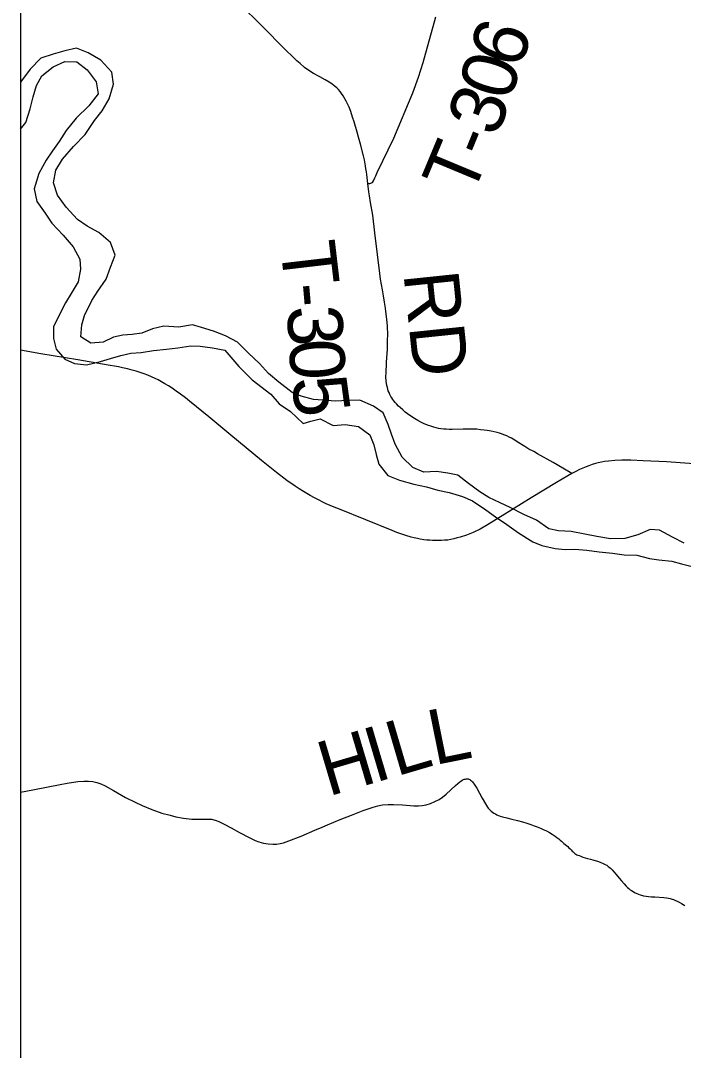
# Model space of a CAD drawing. Extents: x -10.5 to 40.6, y -3.2 to 22.
# Drawn here: x -10.544 to -9.859, y 17.758 to 18.823 of the extents above; entities that cross this region are included whole.
import ezdxf

# ---------------------------------------------------------------- set-up
doc = ezdxf.new("R2010")
doc.units = 0
for name, color, linetype in [('GM_X_Major_River', 7, 'Continuous'), ('GM_X_State_Route', 7, 'Continuous'), ('GM_X_Township_Road', 7, 'Continuous'), ('GM_X_Township_Road_Text', 7, 'Continuous'), ('GM_X_Township_Text', 7, 'Continuous')]:
    doc.layers.add(name, color=color, linetype=linetype)

msp = doc.modelspace()

# ---------------------------------------------------------------- linework, layer by layer
at = {"layer": 'GM_X_Major_River'}
for points in [[(-10.1795, 18.4239), (-10.1936, 18.4301), (-10.2057, 18.4296), (-10.219, 18.429), (-10.2319, 18.43), (-10.2418, 18.4306), (-10.2543, 18.4343), (-10.2638, 18.4379), (-10.2776, 18.4487), (-10.288, 18.4577), (-10.2976, 18.4678), (-10.3088, 18.4786), (-10.3203, 18.4899), (-10.3325, 18.4965), (-10.3451, 18.5013), (-10.3573, 18.5053), (-10.3668, 18.5078), (-10.3808, 18.5057), (-10.3963, 18.5067), (-10.408, 18.5039), (-10.419, 18.4995), (-10.4292, 18.4979), (-10.4387, 18.4974), (-10.4485, 18.4953), (-10.459, 18.4899), (-10.4719, 18.489), (-10.4822, 18.4956), (-10.4813, 18.5078), (-10.4784, 18.5177), (-10.471, 18.533), (-10.4647, 18.5429), (-10.4561, 18.5552), (-10.4514, 18.5677), (-10.4466, 18.5799), (-10.4517, 18.5931), (-10.4636, 18.6036), (-10.4758, 18.6099), (-10.4858, 18.617), (-10.4973, 18.6297), (-10.5062, 18.6421), (-10.5106, 18.6549), (-10.5081, 18.6679), (-10.501, 18.6793), (-10.4899, 18.6924), (-10.4779, 18.7047), (-10.4682, 18.7192), (-10.46, 18.7292), (-10.453, 18.7418), (-10.4483, 18.7567), (-10.45, 18.7691), (-10.4615, 18.7815), (-10.4745, 18.7893), (-10.4867, 18.7941), (-10.4988, 18.7912), (-10.5109, 18.788), (-10.5237, 18.7837), (-10.5345, 18.7722), (-10.5445, 18.759)], [(-10.5445, 18.7103), (-10.5391, 18.7171), (-10.5347, 18.7312), (-10.5315, 18.7438), (-10.5279, 18.7556), (-10.5227, 18.7655), (-10.5107, 18.7748), (-10.4986, 18.7802), (-10.4865, 18.78), (-10.4758, 18.7718), (-10.4665, 18.7594), (-10.4644, 18.747), (-10.4741, 18.7343), (-10.4872, 18.7216), (-10.4973, 18.709), (-10.5047, 18.6975), (-10.5114, 18.6879), (-10.5181, 18.6783), (-10.5255, 18.6646), (-10.5306, 18.6486), (-10.5277, 18.6354), (-10.5192, 18.6233), (-10.5123, 18.6132), (-10.5004, 18.6008), (-10.4903, 18.5885), (-10.4833, 18.5757), (-10.4824, 18.5654), (-10.4849, 18.5525), (-10.4923, 18.5403), (-10.4979, 18.5307), (-10.5045, 18.5181), (-10.5104, 18.5059), (-10.5103, 18.4938), (-10.5078, 18.4828), (-10.4986, 18.4723), (-10.4887, 18.4679), (-10.4765, 18.4665), (-10.4618, 18.4701), (-10.4516, 18.4733), (-10.441, 18.4761), (-10.4305, 18.4785), (-10.4198, 18.4794), (-10.407, 18.4815), (-10.3937, 18.4828), (-10.382, 18.4841), (-10.3684, 18.4862), (-10.3589, 18.4859), (-10.346, 18.4842), (-10.3334, 18.4817), (-10.319, 18.4649), (-10.305, 18.451), (-10.2856, 18.4362), (-10.2771, 18.4262), (-10.2654, 18.4184), (-10.2522, 18.406), (-10.2445, 18.4083), (-10.2347, 18.4106)], [(-9.8583, 18.2822), (-9.8705, 18.2885), (-9.8839, 18.2955), (-9.8934, 18.2962), (-9.9062, 18.2907), (-9.9198, 18.2871), (-9.9346, 18.2865), (-9.9487, 18.289), (-9.9612, 18.2914), (-9.9753, 18.2943), (-9.9882, 18.2949), (-9.9984, 18.297), (-10.0111, 18.3059), (-10.024, 18.3118), (-10.0382, 18.3192), (-10.0485, 18.324), (-10.0603, 18.3295), (-10.0698, 18.3351), (-10.0813, 18.3437), (-10.0925, 18.3526), (-10.1027, 18.3544), (-10.1145, 18.3561), (-10.1274, 18.3556), (-10.1388, 18.3603), (-10.15, 18.3712), (-10.1573, 18.3847), (-10.1609, 18.3949), (-10.1644, 18.4048), (-10.1695, 18.4168), (-10.1795, 18.4239)], [(-10.2347, 18.4106), (-10.2213, 18.404), (-10.2088, 18.4049), (-10.1951, 18.4028), (-10.1833, 18.3943), (-10.1793, 18.3837), (-10.1769, 18.3739), (-10.1741, 18.364), (-10.1649, 18.352), (-10.1527, 18.3473), (-10.1378, 18.3433), (-10.1249, 18.3404), (-10.1131, 18.3368), (-10.1013, 18.3347), (-10.0876, 18.3303), (-10.0773, 18.3259), (-10.0635, 18.3166), (-10.0536, 18.3095), (-10.0417, 18.3014), (-10.0298, 18.2928), (-10.0149, 18.2835), (-10.0054, 18.2798), (-9.9917, 18.2766), (-9.9815, 18.2756), (-9.9716, 18.2758), (-9.9591, 18.2748), (-9.9462, 18.2731), (-9.9325, 18.2717), (-9.9203, 18.27), (-9.9075, 18.2698), (-9.8941, 18.2662), (-9.8846, 18.2648), (-9.871, 18.2635), (-9.8611, 18.2609), (-9.8489, 18.2577)]]:
    msp.add_lwpolyline(points, dxfattribs=at)
at = {"layer": 'GM_X_State_Route'}
msp.add_lwpolyline([(-9.8338, 18.3633), (-9.8767, 18.3661), (-9.9009, 18.3674), (-9.9134, 18.3679), (-9.9227, 18.3681), (-9.9302, 18.3677), (-9.9366, 18.3671), (-9.9406, 18.3666), (-9.944, 18.3658), (-9.9472, 18.3652), (-9.9501, 18.3644), (-9.9535, 18.3634), (-9.9569, 18.3621), (-9.9598, 18.3611), (-9.963, 18.3598), (-9.9667, 18.3582), (-9.9704, 18.3563), (-9.9744, 18.3542), (-9.9786, 18.3519), (-9.9905, 18.345), (-10.0165, 18.3291), (-10.0466, 18.3104), (-10.0619, 18.301), (-10.0694, 18.2968), (-10.0767, 18.2933), (-10.0835, 18.2906), (-10.09, 18.2885), (-10.0932, 18.2876), (-10.0964, 18.2867), (-10.0995, 18.286), (-10.1029, 18.2854), (-10.1062, 18.2851), (-10.1092, 18.2849), (-10.1122, 18.2849), (-10.1153, 18.2849), (-10.1186, 18.285), (-10.1214, 18.2851), (-10.1243, 18.2853), (-10.1277, 18.2857), (-10.1312, 18.2863), (-10.1342, 18.2869), (-10.1376, 18.2876), (-10.1408, 18.2885), (-10.1461, 18.2901), (-10.1504, 18.2915), (-10.1554, 18.2933), (-10.1603, 18.2951), (-10.2148, 18.3172), (-10.2203, 18.3194), (-10.2245, 18.3212), (-10.2284, 18.3229), (-10.2321, 18.3247), (-10.2358, 18.3266), (-10.2407, 18.3291), (-10.245, 18.3314), (-10.2486, 18.3335), (-10.2521, 18.3357), (-10.2566, 18.3384), (-10.2605, 18.341), (-10.2691, 18.3471), (-10.2799, 18.3553), (-10.2953, 18.3678), (-10.327, 18.3939), (-10.35, 18.4129), (-10.3697, 18.4291), (-10.3741, 18.4326), (-10.3791, 18.4363), (-10.3835, 18.4395), (-10.3877, 18.4424), (-10.3916, 18.4448), (-10.3952, 18.447), (-10.3988, 18.4491), (-10.4023, 18.4509), (-10.4055, 18.4525), (-10.4091, 18.4541), (-10.4131, 18.4559), (-10.4167, 18.4573), (-10.4209, 18.4588), (-10.425, 18.4601), (-10.4293, 18.4612), (-10.4341, 18.4624), (-10.4392, 18.4636), (-10.4433, 18.4644), (-10.4474, 18.4652), (-10.452, 18.466), (-10.4597, 18.4673), (-10.4854, 18.4716), (-10.5234, 18.4781), (-10.5445, 18.4818)], dxfattribs=at)
at = {"layer": 'GM_X_Township_Road'}
for points in [[(-10.1855, 18.654), (-10.1862, 18.6602), (-10.1865, 18.6633), (-10.1869, 18.6663), (-10.1874, 18.6693), (-10.1878, 18.6724), (-10.189, 18.6785), (-10.1899, 18.6827), (-10.1931, 18.6947), (-10.1951, 18.7019), (-10.1966, 18.7073), (-10.1996, 18.718), (-10.2012, 18.7227), (-10.2032, 18.7285), (-10.2049, 18.7332), (-10.2079, 18.7393), (-10.211, 18.7447), (-10.2126, 18.7473), (-10.2142, 18.7493), (-10.2158, 18.7513), (-10.2175, 18.753), (-10.2202, 18.7552), (-10.2228, 18.7571), (-10.2256, 18.7589), (-10.2297, 18.7613), (-10.2352, 18.7643), (-10.2416, 18.768), (-10.2474, 18.7717), (-10.2509, 18.7742), (-10.2556, 18.7782), (-10.2588, 18.7811), (-10.2621, 18.7842), (-10.2714, 18.793), (-10.2762, 18.7979), (-10.2896, 18.8117), (-10.2988, 18.8209), (-10.3142, 18.8362)], [(-10.1855, 18.654), (-10.1833, 18.654), (-10.1807, 18.6551), (-10.1795, 18.657), (-10.1781, 18.66), (-10.1772, 18.6621), (-10.1757, 18.6654), (-10.1587, 18.7009), (-10.1391, 18.7477), (-10.133, 18.7641), (-10.1282, 18.7793), (-10.1152, 18.8266)], [(-9.9744, 18.3542), (-9.9838, 18.3597), (-9.9937, 18.3655), (-10.0102, 18.3747), (-10.014, 18.3768), (-10.0189, 18.3795), (-10.0232, 18.3821), (-10.0311, 18.3871), (-10.0336, 18.3887), (-10.0369, 18.3906), (-10.0395, 18.3919), (-10.0419, 18.3931), (-10.0447, 18.3942), (-10.0471, 18.3951), (-10.0494, 18.3958), (-10.0519, 18.3965), (-10.0547, 18.3972), (-10.058, 18.3979), (-10.062, 18.3986), (-10.0653, 18.3991), (-10.069, 18.3995), (-10.0727, 18.3999), (-10.076, 18.4001), (-10.0802, 18.4002), (-10.087, 18.4), (-10.0982, 18.3996), (-10.1013, 18.3996), (-10.1044, 18.3999), (-10.107, 18.4001), (-10.1099, 18.4005), (-10.1123, 18.4009), (-10.1148, 18.4014), (-10.1173, 18.4021), (-10.1202, 18.403), (-10.1227, 18.4039), (-10.1254, 18.4049), (-10.128, 18.406), (-10.1305, 18.4073), (-10.1337, 18.409), (-10.1373, 18.4111), (-10.1411, 18.4136), (-10.1444, 18.416), (-10.1467, 18.4177), (-10.1492, 18.4199), (-10.1519, 18.4223), (-10.1538, 18.424), (-10.1558, 18.4261), (-10.1573, 18.4277), (-10.1585, 18.4292), (-10.1596, 18.4306), (-10.1607, 18.4325), (-10.1617, 18.434), (-10.1626, 18.4358), (-10.1635, 18.4379), (-10.1643, 18.4398), (-10.1653, 18.4433), (-10.1658, 18.4453), (-10.1662, 18.4476), (-10.1665, 18.4495), (-10.1666, 18.4512), (-10.1667, 18.4527), (-10.1667, 18.4552), (-10.1666, 18.4574), (-10.166, 18.4692), (-10.1653, 18.4828), (-10.1651, 18.4883), (-10.165, 18.492), (-10.1649, 18.4976), (-10.1652, 18.5066), (-10.1658, 18.5137), (-10.1668, 18.5216), (-10.1673, 18.5252), (-10.1682, 18.5313), (-10.1694, 18.538), (-10.1704, 18.5441), (-10.1714, 18.5496), (-10.1722, 18.5551), (-10.1731, 18.5612), (-10.1756, 18.5806), (-10.1781, 18.603), (-10.1803, 18.6213), (-10.1826, 18.6346), (-10.1836, 18.6414), (-10.1843, 18.6456), (-10.1855, 18.654)], [(-10.5445, 18.0246), (-10.5317, 18.0271), (-10.5159, 18.0303), (-10.5037, 18.0327), (-10.4963, 18.034), (-10.4853, 18.0357), (-10.4791, 18.0362), (-10.4742, 18.0362), (-10.4698, 18.0357), (-10.4656, 18.0348), (-10.4615, 18.0334), (-10.457, 18.0313), (-10.4483, 18.0265), (-10.4359, 18.0193), (-10.426, 18.0142), (-10.4187, 18.0108), (-10.4089, 18.0069), (-10.3984, 18.0031), (-10.39, 18.0007), (-10.384, 17.9993), (-10.376, 17.9979), (-10.3674, 17.9969), (-10.3611, 17.9966), (-10.3554, 17.9968), (-10.3508, 17.9967), (-10.347, 17.9966), (-10.3432, 17.9958), (-10.3395, 17.9944), (-10.3339, 17.9916), (-10.3266, 17.9876), (-10.318, 17.9828), (-10.3082, 17.9777), (-10.3021, 17.9748), (-10.2981, 17.9733), (-10.2933, 17.972), (-10.2884, 17.9713), (-10.2835, 17.9709), (-10.2798, 17.971), (-10.2761, 17.9715), (-10.2725, 17.9724), (-10.2672, 17.9742), (-10.2544, 17.9792), (-10.2402, 17.9853), (-10.2328, 17.9885), (-10.2271, 17.991), (-10.214, 17.9964), (-10.2025, 18.001), (-10.1904, 18.0056), (-10.1798, 18.0092), (-10.175, 18.0105), (-10.1702, 18.0114), (-10.1646, 18.0119), (-10.159, 18.0119), (-10.1497, 18.0114), (-10.1379, 18.0105), (-10.133, 18.0105), (-10.1293, 18.0109), (-10.125, 18.0117), (-10.1208, 18.013), (-10.1162, 18.0149), (-10.1118, 18.0172), (-10.1082, 18.0196), (-10.1044, 18.0227), (-10.0947, 18.0315), (-10.0925, 18.0336), (-10.0905, 18.0352), (-10.0892, 18.0362), (-10.088, 18.037), (-10.0868, 18.0376), (-10.0857, 18.038), (-10.0849, 18.0382), (-10.0839, 18.0384), (-10.0826, 18.0385), (-10.0818, 18.0383), (-10.0809, 18.038), (-10.0801, 18.0376), (-10.0793, 18.0371), (-10.0783, 18.0364), (-10.0774, 18.0355), (-10.0765, 18.0342), (-10.0756, 18.033), (-10.0729, 18.0288), (-10.0673, 18.0185), (-10.0639, 18.0125), (-10.0627, 18.0108), (-10.0617, 18.0092), (-10.0609, 18.0082), (-10.0602, 18.0075), (-10.059, 18.0061), (-10.0579, 18.0051), (-10.0567, 18.0041), (-10.0552, 18.0031), (-10.0536, 18.0021), (-10.0521, 18.0013), (-10.0503, 18.0006), (-10.0485, 18), (-10.0462, 17.9992), (-10.0416, 17.998), (-10.0366, 17.9968), (-10.0306, 17.9953), (-10.0257, 17.994), (-10.021, 17.9926), (-10.0168, 17.9912), (-10.0134, 17.99), (-10.0104, 17.9889), (-10.0071, 17.9875), (-10.0042, 17.9862), (-10.0009, 17.9845), (-9.9978, 17.9828), (-9.995, 17.9811), (-9.9917, 17.979), (-9.9899, 17.9776), (-9.988, 17.9763), (-9.9865, 17.9751), (-9.9853, 17.974), (-9.9842, 17.973), (-9.9827, 17.9717), (-9.9813, 17.9705), (-9.9799, 17.9694), (-9.9788, 17.9684), (-9.9776, 17.9672), (-9.9764, 17.9662), (-9.9752, 17.9649), (-9.9741, 17.9638), (-9.9731, 17.9629), (-9.9721, 17.962), (-9.9713, 17.9613), (-9.9703, 17.9606), (-9.9692, 17.96), (-9.9682, 17.9595), (-9.9671, 17.959), (-9.9654, 17.9584), (-9.963, 17.9576), (-9.9608, 17.9569), (-9.9582, 17.9562), (-9.9553, 17.9553), (-9.9529, 17.9546), (-9.9469, 17.9528), (-9.9446, 17.952), (-9.9429, 17.9513), (-9.9415, 17.9507), (-9.9401, 17.9499), (-9.9385, 17.949), (-9.937, 17.9479), (-9.9359, 17.9472), (-9.9346, 17.946), (-9.933, 17.9443), (-9.9312, 17.9424), (-9.9286, 17.9394), (-9.9257, 17.9358), (-9.9233, 17.9331), (-9.9204, 17.9297), (-9.9185, 17.9276), (-9.917, 17.9261), (-9.9157, 17.925), (-9.9142, 17.9238), (-9.9127, 17.9228), (-9.9111, 17.9218), (-9.9096, 17.921), (-9.9072, 17.9199), (-9.9057, 17.9192), (-9.9038, 17.9186), (-9.9024, 17.9181), (-9.9003, 17.9176), (-9.8978, 17.9172), (-9.8954, 17.9169), (-9.8922, 17.9165), (-9.8887, 17.9163), (-9.8794, 17.9157), (-9.8768, 17.9154), (-9.8745, 17.915), (-9.8729, 17.9147), (-9.8709, 17.9141), (-9.8694, 17.9136), (-9.868, 17.913), (-9.8655, 17.9118), (-9.8636, 17.9108), (-9.8612, 17.9094), (-9.8578, 17.9074)]]:
    msp.add_lwpolyline(points, dxfattribs=at)
at = {"layer": 'GM_X_Township_Text'}
msp.add_lwpolyline([(-10.5445, 19.4241), (-10.5445, 16.0741), (-10.3151, 16.0685), (-10.1031, 16.0664), (-9.5534, 16.0497), (-8.7017, 16.0275), (-8.5879, 16.0247), (-8.2615, 16.0223), (-8.2451, 17.3912), (-8.2441, 17.4134)], dxfattribs=at)

# ---------------------------------------------------------------- texts
at = {"layer": 'GM_X_Township_Road_Text'}
for s, height, rotation, p in [('6', 0.0568, 71.2014, (-10.0283, 18.7709)), ('0', 0.0568, 73.1596, (-10.0383, 18.7379)), ('3', 0.0568, 68.8954, (-10.0524, 18.7009)), ('T', 0.0568, 67.4035, (-10.0781, 18.6386)), ('-', 0.0568, 67.7199, (-10.0617, 18.6781)), ('T', 0.0568, 276.7051, (-10.2763, 18.5912)), ('RD', 0.05682, 275.9567, (-10.1487, 18.561)), ('-', 0.0568, 275.01, (-10.2714, 18.5494)), ('3', 0.0568, 273.5306, (-10.2693, 18.5266)), ('0', 0.0568, 273.3167, (-10.2672, 18.4917)), ('5', 0.0568, 277.7716, (-10.2647, 18.452)), ('L', 0.0568, 11.3889, (-10.1167, 18.0525)), ('L', 0.0568, 16.4099, (-10.1562, 18.0408)), ('H', 0.0568, 16.5293, (-10.2265, 18.02)), ('I', 0.0568, 16.5347, (-10.1785, 18.0342))]:
    msp.add_text(s, height=height, rotation=rotation, dxfattribs=at).set_placement(p)

doc.saveas('drawing.dxf')
